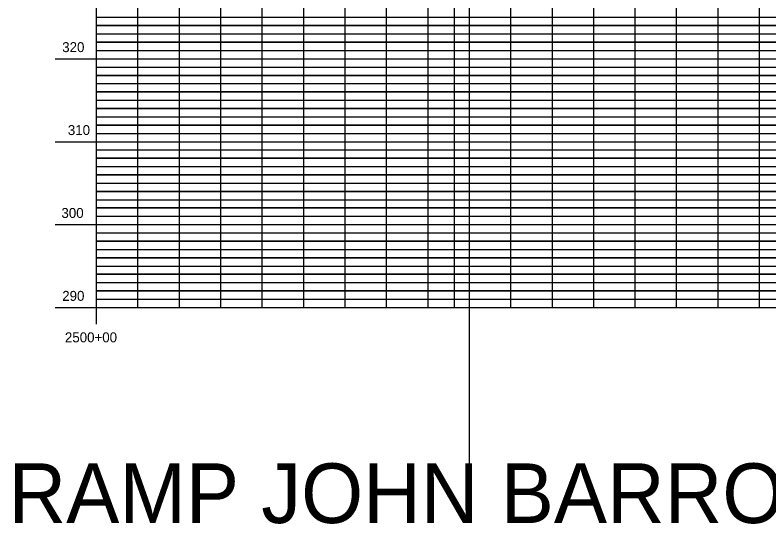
# Model space of a CAD drawing. Extents: x 1195880 to 1289360, y 2059330 to 2086925.
# Drawn here: x 1203065.2 to 1203520, y 2064733.7 to 2065040.5 of the extents above; entities that cross this region are included whole.
import ezdxf

# ---------------------------------------------------------------- set-up
doc = ezdxf.new("R2010")
doc.units = 0
for name, color, linetype in [('51', 7, 'Continuous'), ('Default', 7, 'Continuous'), ('Grid', 7, 'Continuous'), ('Grid Lables', 7, 'Continuous')]:
    doc.layers.add(name, color=color, linetype=linetype)

msp = doc.modelspace()

# ---------------------------------------------------------------- linework, layer by layer
at = {"layer": 'Default'}
for p, q in [((1203330.32, 2064864.18), (1203330.32, 2065810.63)), ((1203114.36, 2064864.18), (1203330.32, 2064864.18))]:
    msp.add_line(p, q, dxfattribs=at)
at = {"layer": 'Grid'}
for p, q in [((1203114.36, 2064864.18), (1203114.36, 2065664.18)), ((1203139.36, 2064864.18), (1203139.36, 2065664.18)), ((1203164.36, 2064864.18), (1203164.36, 2065664.18)), ((1203189.36, 2064864.18), (1203189.36, 2065664.18)), ((1203214.36, 2064864.18), (1203214.36, 2065664.18)), ((1203239.36, 2064864.18), (1203239.36, 2065664.18)), ((1203264.36, 2064864.18), (1203264.36, 2065664.18)), ((1203289.36, 2064864.18), (1203289.36, 2065664.18)), ((1203314.36, 2064864.18), (1203314.36, 2065664.18)), ((1203364.36, 2064864.18), (1203364.36, 2065664.18)), ((1203389.36, 2064864.18), (1203389.36, 2065664.18)), ((1203414.36, 2064864.18), (1203414.36, 2065664.18)), ((1203439.36, 2064864.18), (1203439.36, 2065664.18)), ((1203464.36, 2064864.18), (1203464.36, 2065664.18)), ((1203489.36, 2064864.18), (1203489.36, 2065664.18)), ((1203514.36, 2064864.18), (1203514.36, 2065664.18)), ((1203339.36, 2064764.18), (1203339.36, 2065564.18)), ((1203114.36, 2065039.18), (1203117.36, 2065039.18)), ((1203114.36, 2065039.18), (1204114.36, 2065039.18)), ((1203114.36, 2065034.18), (1203117.36, 2065034.18)), ((1203114.36, 2065034.18), (1204114.36, 2065034.18)), ((1204114.36, 2065034.18), (1203114.36, 2065034.18)), ((1203114.36, 2065029.18), (1203117.36, 2065029.18)), ((1203114.36, 2065029.18), (1204114.36, 2065029.18)), ((1203114.36, 2065024.18), (1203117.36, 2065024.18)), ((1203114.36, 2065024.18), (1204114.36, 2065024.18)), ((1204114.36, 2065024.18), (1203114.36, 2065024.18)), ((1203114.36, 2065019.18), (1203117.36, 2065019.18)), ((1203114.36, 2065019.18), (1204114.36, 2065019.18)), ((1203089.36, 2065014.18), (1203114.36, 2065014.18)), ((1203114.36, 2065014.18), (1204114.36, 2065014.18)), ((1203114.36, 2065009.18), (1203117.36, 2065009.18)), ((1203114.36, 2065009.18), (1204114.36, 2065009.18)), ((1203114.36, 2065004.18), (1203117.36, 2065004.18)), ((1203114.36, 2065004.18), (1204114.36, 2065004.18)), ((1204114.36, 2065004.18), (1203114.36, 2065004.18)), ((1203114.36, 2064999.18), (1203117.36, 2064999.18)), ((1203114.36, 2064999.18), (1204114.36, 2064999.18)), ((1203114.36, 2064994.18), (1203117.36, 2064994.18)), ((1203114.36, 2064994.18), (1204114.36, 2064994.18)), ((1204114.36, 2064994.18), (1203114.36, 2064994.18)), ((1203114.36, 2064989.18), (1203117.36, 2064989.18)), ((1203114.36, 2064989.18), (1204114.36, 2064989.18)), ((1203114.36, 2064984.18), (1203117.36, 2064984.18)), ((1203114.36, 2064984.18), (1204114.36, 2064984.18)), ((1204114.36, 2064984.18), (1203114.36, 2064984.18)), ((1203114.36, 2064979.18), (1203117.36, 2064979.18)), ((1203114.36, 2064979.18), (1204114.36, 2064979.18)), ((1203114.36, 2064974.18), (1203117.36, 2064974.18)), ((1203114.36, 2064974.18), (1204114.36, 2064974.18)), ((1204114.36, 2064974.18), (1203114.36, 2064974.18)), ((1203114.36, 2064969.18), (1203117.36, 2064969.18)), ((1203114.36, 2064969.18), (1204114.36, 2064969.18)), ((1203089.36, 2064964.18), (1203114.36, 2064964.18)), ((1203114.36, 2064964.18), (1204114.36, 2064964.18)), ((1203114.36, 2064959.18), (1203117.36, 2064959.18)), ((1203114.36, 2064959.18), (1204114.36, 2064959.18)), ((1203114.36, 2064954.18), (1203117.36, 2064954.18)), ((1203114.36, 2064954.18), (1204114.36, 2064954.18)), ((1204114.36, 2064954.18), (1203114.36, 2064954.18)), ((1203114.36, 2064949.18), (1203117.36, 2064949.18)), ((1203114.36, 2064949.18), (1204114.36, 2064949.18)), ((1203114.36, 2064944.18), (1203117.36, 2064944.18)), ((1203114.36, 2064944.18), (1204114.36, 2064944.18)), ((1204114.36, 2064944.18), (1203114.36, 2064944.18)), ((1203114.36, 2064939.18), (1203117.36, 2064939.18)), ((1203114.36, 2064939.18), (1204114.36, 2064939.18)), ((1203114.36, 2064934.18), (1203117.36, 2064934.18)), ((1203114.36, 2064934.18), (1204114.36, 2064934.18)), ((1204114.36, 2064934.18), (1203114.36, 2064934.18)), ((1203114.36, 2064929.18), (1203117.36, 2064929.18)), ((1203114.36, 2064929.18), (1204114.36, 2064929.18)), ((1203114.36, 2064924.18), (1203117.36, 2064924.18)), ((1203114.36, 2064924.18), (1204114.36, 2064924.18)), ((1204114.36, 2064924.18), (1203114.36, 2064924.18)), ((1203114.36, 2064919.18), (1203117.36, 2064919.18)), ((1203114.36, 2064919.18), (1204114.36, 2064919.18)), ((1203089.36, 2064914.18), (1203114.36, 2064914.18)), ((1203114.36, 2064914.18), (1204114.36, 2064914.18)), ((1203114.36, 2064909.18), (1203117.36, 2064909.18)), ((1203114.36, 2064909.18), (1204114.36, 2064909.18)), ((1203114.36, 2064904.18), (1203117.36, 2064904.18)), ((1203114.36, 2064904.18), (1204114.36, 2064904.18)), ((1204114.36, 2064904.18), (1203114.36, 2064904.18)), ((1203114.36, 2064899.18), (1203117.36, 2064899.18)), ((1203114.36, 2064899.18), (1204114.36, 2064899.18)), ((1203114.36, 2064894.18), (1203117.36, 2064894.18)), ((1203114.36, 2064894.18), (1204114.36, 2064894.18)), ((1204114.36, 2064894.18), (1203114.36, 2064894.18)), ((1203114.36, 2064889.18), (1203117.36, 2064889.18)), ((1203114.36, 2064889.18), (1204114.36, 2064889.18)), ((1203114.36, 2064884.18), (1203117.36, 2064884.18)), ((1203114.36, 2064884.18), (1204114.36, 2064884.18)), ((1204114.36, 2064884.18), (1203114.36, 2064884.18)), ((1203114.36, 2064879.18), (1203117.36, 2064879.18)), ((1203114.36, 2064879.18), (1204114.36, 2064879.18)), ((1203114.36, 2064874.18), (1203117.36, 2064874.18)), ((1203114.36, 2064874.18), (1204114.36, 2064874.18)), ((1204114.36, 2064874.18), (1203114.36, 2064874.18)), ((1203114.36, 2064869.18), (1203117.36, 2064869.18)), ((1203114.36, 2064869.18), (1204114.36, 2064869.18)), ((1203089.36, 2064864.18), (1203114.36, 2064864.18)), ((1203114.36, 2064864.18), (1204114.36, 2064864.18)), ((1203114.36, 2064854.18), (1203114.36, 2064864.18)), ((1203139.36, 2064864.18), (1203139.36, 2064867.18)), ((1203164.36, 2064864.18), (1203164.36, 2064867.18)), ((1203189.36, 2064864.18), (1203189.36, 2064867.18)), ((1203214.36, 2064864.18), (1203214.36, 2064867.18)), ((1203239.36, 2064864.18), (1203239.36, 2064867.18)), ((1203264.36, 2064864.18), (1203264.36, 2064867.18)), ((1203289.36, 2064864.18), (1203289.36, 2064867.18)), ((1203314.36, 2064864.18), (1203314.36, 2064867.18)), ((1203339.36, 2064864.18), (1203339.36, 2064867.18)), ((1203364.36, 2064864.18), (1203364.36, 2064867.18)), ((1203389.36, 2064864.18), (1203389.36, 2064867.18)), ((1203414.36, 2064864.18), (1203414.36, 2064867.18)), ((1203439.36, 2064864.18), (1203439.36, 2064867.18)), ((1203464.36, 2064864.18), (1203464.36, 2064867.18)), ((1203489.36, 2064864.18), (1203489.36, 2064867.18)), ((1203514.36, 2064864.18), (1203514.36, 2064867.18))]:
    msp.add_line(p, q, dxfattribs=at)

# ---------------------------------------------------------------- texts
at = {"layer": '51'}
msp.add_text('-', height=0.0001, dxfattribs=at).set_placement((1203114.36, 2064864.18))
at = {"layer": 'Default'}
msp.add_text('RAMP JOHN BARROW RD TO EB I-630', height=36, rotation=360, dxfattribs=at).set_placement((1203061.28, 2064734.18))
at = {"layer": 'Grid Lables'}
for s, p in [('320', (1203093.67, 2065018.18)), ('310', (1203097.07, 2064968.18)), ('300', (1203093.2, 2064918.18)), ('290', (1203093.67, 2064868.18)), ('2500+00', (1203095.3, 2064843.18))]:
    msp.add_text(s, height=6, dxfattribs=at).set_placement(p)

doc.saveas('drawing.dxf')
